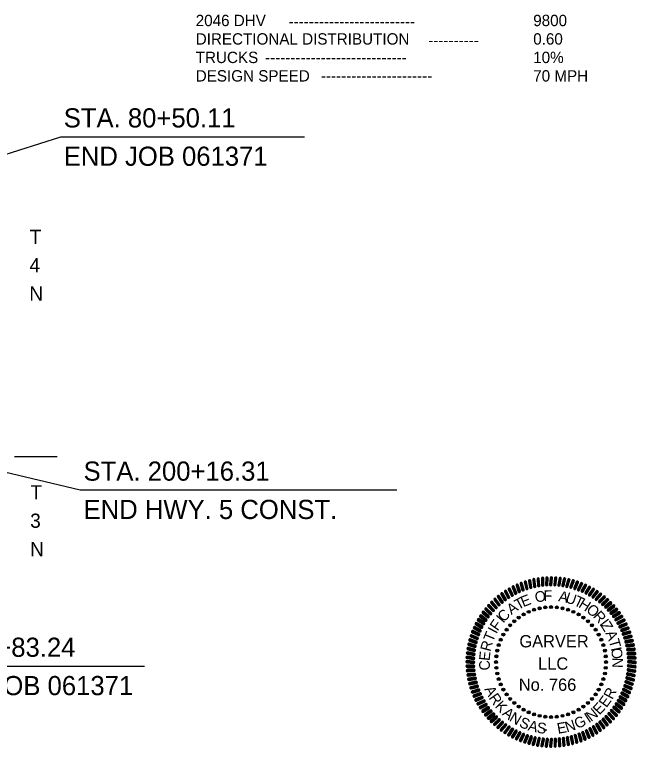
# Model space of a CAD drawing. Extents: x 1373878 to 1386598, y 1168333 to 1170533.
# Drawn here: x 1376117 to 1376992, y 1168417 to 1169449 of the extents above; entities that cross this region are included whole.
import ezdxf

# ---------------------------------------------------------------- set-up
doc = ezdxf.new("R2010")
doc.units = 0
for name, color, linetype in [('G-ANNO-STMP', 7, 'Continuous'), ('G-ANNO-TEXT', 7, 'Continuous'), ('R_Dimension', 7, 'Continuous'), ('R_Draft', 7, 'Continuous')]:
    doc.layers.add(name, color=color, linetype=linetype)

# ---------------------------------------------------------------- blocks, each defined once
blk = doc.blocks.new('SEALDO')
at = {"layer": 'G-ANNO-TEXT'}
for radius in [0.0396, 0.0305, 0.0213, 0.0122, 0.00305]:
    blk.add_circle((1.403, -0.456), radius, dxfattribs=at)
blk = doc.blocks.new('SEALRI')
at = {"layer": 'G-ANNO-TEXT'}
for p, q in [((-0.023, 2.258), (-0.038, 2.081)), ((-0.008, 2.281), (-0.028, 2.056)), ((0.004, 2.286), (-0.016, 2.049)), ((0.016, 2.285), (-0.004, 2.048)), ((0.028, 2.278), (0.008, 2.052)), ((0.023, 2.076), (0.038, 2.253))]:
    blk.add_line(p, q, dxfattribs=at)
for centre, start, end in [((0.008, 2.256), 355, 175), ((-0.008, 2.078), 175, 355)]:
    blk.add_arc(centre, 0.0305, start, end, dxfattribs=at)

msp = doc.modelspace()

# ---------------------------------------------------------------- linework, layer by layer
at = {"layer": 'R_Dimension'}
msp.add_line((1376117.2, 1168826.8), (1376177.2, 1168826.8), dxfattribs=at)
at = {"layer": 'R_Draft'}
for p, q in [((1376181.5, 1169276.8), (1375395.5, 1169025.7)), ((1376525.3, 1169276.8), (1376181.5, 1169276.8)), ((1376209.4, 1168779.3), (1375377.1, 1168978.1)), ((1376655.3, 1168779.3), (1376209.4, 1168779.3)), ((1376299.9, 1168531.2), (1375956.2, 1168531.2))]:
    msp.add_line(p, q, dxfattribs=at)

# ---------------------------------------------------------------- block references
at = {"layer": 'G-ANNO-STMP'}
for name, xscale, yscale, rotation in [('SEALRI', 52.49240596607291, 52.4924059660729, 20.99999999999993), ('SEALRI', 52.492405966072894, 52.4924059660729, 18), ('SEALRI', 52.4924059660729, 52.4924059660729, 15.000000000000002), ('SEALRI', 52.492405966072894, 52.492405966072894, 12.000000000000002), ('SEALRI', 52.492405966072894, 52.49240596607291, 9), ('SEALRI', 52.492405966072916, 52.49240596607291, 6), ('SEALRI', 52.492405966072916, 52.492405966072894, 3.0000000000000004), ('SEALRI', 52.49240596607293, 52.49240596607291, -2.9999999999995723), ('SEALRI', 52.4924059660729, 52.49240596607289, -5.9999999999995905), ('SEALRI', 52.492405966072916, 52.49240596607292, -8.999999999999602), ('SEALRI', 52.492405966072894, 52.492405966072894, -11.999999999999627), ('SEALRI', 52.4924059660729, 52.492405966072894, -14.999999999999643), ('SEALRI', 52.4924059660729, 52.4924059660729, -17.999999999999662), ('SEALRI', 52.4924059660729, 52.492405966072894, -20.999999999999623), ('SEALRI', 52.4924059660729, 52.492405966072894, 33), ('SEALRI', 52.4924059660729, 52.492405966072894, 30.00000000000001), ('SEALRI', 52.492405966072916, 52.492405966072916, 26.999999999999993), ('SEALRI', 52.49240596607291, 52.4924059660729, 23.99999999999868), ('SEALRI', 52.492405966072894, 52.4924059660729, -23.99999999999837), ('SEALRI', 52.492405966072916, 52.49240596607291, -26.9999999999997), ('SEALRI', 52.4924059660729, 52.49240596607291, -29.99999999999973), ('SEALRI', 52.4924059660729, 52.49240596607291, -32.999999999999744), ('SEALRI', 52.49240596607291, 52.4924059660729, 41.999999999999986), ('SEALRI', 52.49240596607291, 52.4924059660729, 38.999999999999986), ('SEALRI', 52.4924059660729, 52.492405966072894, 36), ('SEALRI', 52.4924059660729, 52.492405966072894, -35.999999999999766), ('SEALRI', 52.4924059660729, 52.4924059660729, -38.99999999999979), ('SEALRI', 52.4924059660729, 52.4924059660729, -41.99999999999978), ('SEALRI', 52.492405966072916, 52.49240596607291, 47.99999999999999), ('SEALRI', 52.4924059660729, 52.492405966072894, 44.999999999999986), ('SEALDO', 52.4924059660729, 52.49240596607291, 107.99999999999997), ('SEALRI', 52.49240596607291, 52.4924059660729, -44.99999999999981), ('SEALRI', 52.49240596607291, 52.4924059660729, -47.99999999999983), ('SEALRI', 52.4924059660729, 52.492405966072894, 54), ('SEALRI', 52.49240596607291, 52.4924059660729, 50.99999999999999), ('SEALDO', 52.4924059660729, 52.49240596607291, 138), ('SEALDO', 52.492405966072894, 52.49240596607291, 131.99999999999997), ('SEALDO', 52.492405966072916, 52.492405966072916, 125.99999999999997), ('SEALDO', 52.492405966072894, 52.4924059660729, 119.99999999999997), ('SEALDO', 52.4924059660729, 52.49240596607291, 113.99999999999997), ('SEALDO', 52.4924059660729, 52.49240596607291, 101.99999999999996), ('SEALDO', 52.492405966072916, 52.49240596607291, 95.99999999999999), ('SEALDO', 52.49240596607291, 52.4924059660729, 90), ('SEALDO', 52.492405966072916, 52.492405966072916, 83.99999999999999), ('SEALRI', 52.492405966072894, 52.4924059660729, -50.99999999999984), ('SEALRI', 52.4924059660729, 52.4924059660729, -53.99999999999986), ('SEALRI', 52.492405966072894, 52.4924059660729, 59.999999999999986), ('SEALRI', 52.49240596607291, 52.492405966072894, 56.99999999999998), ('SEALDO', 52.49240596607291, 52.4924059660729, 150), ('SEALDO', 52.492405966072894, 52.4924059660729, 144), ('SEALDO', 52.492405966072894, 52.4924059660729, 77.99999999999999), ('SEALDO', 52.492405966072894, 52.4924059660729, 72), ('SEALDO', 52.49240596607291, 52.49240596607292, 66.00000000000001), ('SEALRI', 52.49240596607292, 52.49240596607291, -56.999999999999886), ('SEALRI', 52.4924059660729, 52.4924059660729, -59.99999999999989), ('SEALRI', 52.49240596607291, 52.4924059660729, 65.99999999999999), ('SEALRI', 52.492405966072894, 52.49240596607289, 63), ('SEALDO', 52.4924059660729, 52.49240596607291, 156.00000000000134), ('SEALDO', 52.49240596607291, 52.4924059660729, 60.00000000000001), ('SEALRI', 52.49240596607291, 52.492405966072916, -62.99999999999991), ('SEALRI', 52.49240596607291, 52.49240596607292, -65.99999999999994), ('SEALRI', 52.492405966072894, 52.4924059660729, 72), ('SEALRI', 52.49240596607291, 52.4924059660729, 68.99999999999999), ('SEALDO', 52.49240596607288, 52.4924059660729, 168.00000000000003), ('SEALDO', 52.492405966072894, 52.49240596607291, 162.00000000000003), ('SEALDO', 52.4924059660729, 52.492405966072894, 54), ('SEALDO', 52.49240596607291, 52.4924059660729, 48.000000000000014), ('SEALRI', 52.49240596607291, 52.4924059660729, -68.99999999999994), ('SEALRI', 52.4924059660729, 52.4924059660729, -71.99999999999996), ('SEALRI', 52.4924059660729, 52.49240596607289, 75.00000000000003), ('SEALDO', 52.492405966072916, 52.49240596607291, 174.00000000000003), ('SEALDO', 52.492405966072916, 52.49240596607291, 42.00000000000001), ('SEALRI', 52.49240596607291, 52.4924059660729, -74.99999999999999), ('SEALRI', 52.492405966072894, 52.49240596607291, 81), ('SEALRI', 52.492405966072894, 52.49240596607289, 78.00000000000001), ('SEALDO', 52.49240596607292, 52.49240596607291, -173.99999999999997), ('SEALDO', 52.49240596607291, 52.4924059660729, -179.99999999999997), ('SEALDO', 52.4924059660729, 52.492405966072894, 36), ('SEALDO', 52.49240596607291, 52.4924059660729, 29.999999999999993), ('SEALRI', 52.492405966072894, 52.492405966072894, -78), ('SEALRI', 52.492405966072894, 52.49240596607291, -81.00000000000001), ('SEALRI', 52.4924059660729, 52.49240596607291, 87.00000000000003), ('SEALRI', 52.492405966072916, 52.49240596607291, 84.00000000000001), ('SEALDO', 52.492405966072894, 52.4924059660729, -167.99999999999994), ('SEALDO', 52.49240596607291, 52.4924059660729, 23.99999999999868), ('SEALRI', 52.492405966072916, 52.49240596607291, -84.00000000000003), ('SEALRI', 52.4924059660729, 52.4924059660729, -87.00000000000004), ('SEALRI', 52.49240596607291, 52.4924059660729, 90.00000000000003), ('SEALDO', 52.4924059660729, 52.492405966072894, -161.99999999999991), ('SEALDO', 52.492405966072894, 52.4924059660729, 18), ('SEALRI', 52.49240596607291, 52.4924059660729, -90.00000000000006), ('SEALRI', 52.492405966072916, 52.492405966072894, 93), ('SEALRI', 52.492405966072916, 52.492405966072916, 96.00000000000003), ('SEALDO', 52.4924059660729, 52.4924059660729, -156.00000000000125), ('SEALDO', 52.492405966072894, 52.492405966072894, 12.000000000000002), ('SEALRI', 52.4924059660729, 52.492405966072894, -96.0000000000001), ('SEALRI', 52.492405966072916, 52.49240596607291, -93.00000000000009), ('SEALRI', 52.49240596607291, 52.492405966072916, 99.00000000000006), ('SEALRI', 52.492405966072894, 52.49240596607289, 102.00000000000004), ('SEALDO', 52.4924059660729, 52.49240596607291, -149.99999999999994), ('SEALDO', 52.492405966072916, 52.49240596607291, -143.99999999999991), ('SEALDO', 52.492405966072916, 52.49240596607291, 6), ('SEALRI', 52.492405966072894, 52.492405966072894, -102.00000000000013), ('SEALRI', 52.49240596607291, 52.492405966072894, -99.00000000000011), ('SEALRI', 52.49240596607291, 52.4924059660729, 105.00000000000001), ('SEALRI', 52.4924059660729, 52.4924059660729, 108.00000000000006), ('SEALDO', 52.492405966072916, 52.49240596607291, -137.9999999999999), ('SEALDO', 52.4924059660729, 52.4924059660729, -6.000000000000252), ('SEALRI', 52.49240596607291, 52.492405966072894, -108.00000000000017), ('SEALRI', 52.49240596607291, 52.4924059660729, -105.00000000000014), ('SEALRI', 52.4924059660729, 52.492405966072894, 111.00000000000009), ('SEALRI', 52.49240596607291, 52.492405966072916, 114.00000000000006), ('SEALDO', 52.4924059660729, 52.49240596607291, -131.99999999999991), ('SEALDO', 52.4924059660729, 52.49240596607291, -125.9999999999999), ('SEALDO', 52.492405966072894, 52.4924059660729, -18.000000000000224), ('SEALDO', 52.492405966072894, 52.492405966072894, -12.000000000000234), ('SEALRI', 52.49240596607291, 52.492405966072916, -114.0000000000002), ('SEALRI', 52.4924059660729, 52.49240596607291, -111.00000000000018), ('SEALRI', 52.4924059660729, 52.49240596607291, 117.00000000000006), ('SEALRI', 52.492405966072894, 52.4924059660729, 120.00000000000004), ('SEALDO', 52.4924059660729, 52.4924059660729, -119.99999999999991), ('SEALDO', 52.49240596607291, 52.492405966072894, -23.999999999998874), ('SEALRI', 52.4924059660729, 52.4924059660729, -120.00000000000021), ('SEALRI', 52.49240596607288, 52.4924059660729, -117.00000000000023), ('SEALRI', 52.4924059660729, 52.492405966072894, 123.00000000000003), ('SEALRI', 52.4924059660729, 52.49240596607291, 126.00000000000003), ('SEALDO', 52.49240596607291, 52.492405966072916, -113.99999999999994), ('SEALDO', 52.4924059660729, 52.4924059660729, -107.99999999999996), ('SEALDO', 52.4924059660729, 52.492405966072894, -42.00000000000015), ('SEALDO', 52.4924059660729, 52.4924059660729, -36.00000000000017), ('SEALDO', 52.4924059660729, 52.492405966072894, -30.00000000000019), ('SEALRI', 52.4924059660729, 52.4924059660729, -126.00000000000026), ('SEALRI', 52.492405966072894, 52.49240596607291, -123.00000000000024), ('SEALRI', 52.49240596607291, 52.4924059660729, 129.00000000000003), ('SEALRI', 52.4924059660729, 52.4924059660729, 132), ('SEALRI', 52.4924059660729, 52.49240596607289, 135), ('SEALDO', 52.492405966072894, 52.49240596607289, -101.99999999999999), ('SEALDO', 52.492405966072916, 52.49240596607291, -96), ('SEALDO', 52.49240596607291, 52.4924059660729, -90.00000000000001), ('SEALDO', 52.492405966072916, 52.49240596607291, -84.00000000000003), ('SEALDO', 52.4924059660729, 52.49240596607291, -78.00000000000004), ('SEALDO', 52.4924059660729, 52.49240596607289, -72.00000000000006), ('SEALDO', 52.492405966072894, 52.49240596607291, -66.00000000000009), ('SEALDO', 52.4924059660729, 52.49240596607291, -60.0000000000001), ('SEALDO', 52.4924059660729, 52.4924059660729, -54.000000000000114), ('SEALDO', 52.49240596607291, 52.492405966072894, -48.00000000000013), ('SEALRI', 52.492405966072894, 52.4924059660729, -135.00000000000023), ('SEALRI', 52.49240596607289, 52.4924059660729, -132.00000000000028), ('SEALRI', 52.492405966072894, 52.4924059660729, -129.00000000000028), ('SEALRI', 52.4924059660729, 52.49240596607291, 138), ('SEALRI', 52.492405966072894, 52.4924059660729, 140.99999999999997), ('SEALRI', 52.4924059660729, 52.4924059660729, -141.0000000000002), ('SEALRI', 52.4924059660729, 52.492405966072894, -138.00000000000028), ('SEALRI', 52.492405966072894, 52.4924059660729, 144), ('SEALRI', 52.4924059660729, 52.492405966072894, 146.99999999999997), ('SEALRI', 52.4924059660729, 52.49240596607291, 149.99999999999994), ('SEALRI', 52.492405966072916, 52.49240596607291, 152.99999999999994), ('SEALRI', 52.4924059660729, 52.49240596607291, -153.00000000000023), ('SEALRI', 52.49240596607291, 52.492405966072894, -150.00000000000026), ('SEALRI', 52.4924059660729, 52.49240596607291, -147.00000000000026), ('SEALRI', 52.49240596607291, 52.49240596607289, -144.00000000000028), ('SEALRI', 52.4924059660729, 52.49240596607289, 156.00000000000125), ('SEALRI', 52.4924059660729, 52.4924059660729, 159), ('SEALRI', 52.49240596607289, 52.49240596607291, 161.99999999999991), ('SEALRI', 52.4924059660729, 52.49240596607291, 164.99999999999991), ('SEALRI', 52.492405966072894, 52.49240596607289, 167.99999999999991), ('SEALRI', 52.492405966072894, 52.4924059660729, -168.0000000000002), ('SEALRI', 52.4924059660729, 52.49240596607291, -165.0000000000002), ('SEALRI', 52.4924059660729, 52.4924059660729, -162.0000000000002), ('SEALRI', 52.4924059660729, 52.49240596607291, -159.00000000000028), ('SEALRI', 52.492405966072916, 52.49240596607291, -156.00000000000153), ('SEALRI', 52.49240596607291, 52.492405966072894, 170.9999999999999), ('SEALRI', 52.4924059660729, 52.4924059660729, 173.9999999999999), ('SEALRI', 52.492405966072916, 52.49240596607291, 176.9999999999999), ('SEALRI', 52.49240596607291, 52.4924059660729, 179.99999999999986), ('SEALRI', 52.492405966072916, 52.49240596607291, -177.00000000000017), ('SEALRI', 52.4924059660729, 52.492405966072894, -174.00000000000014), ('SEALRI', 52.49240596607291, 52.49240596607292, -171.00000000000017)]:
    msp.add_blockref(name, (1376872.3, 1168537.3), dxfattribs=dict(at, xscale=xscale, yscale=yscale, rotation=rotation))
at = {"layer": 'G-ANNO-STMP', "xscale": 52.49240596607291, "yscale": 52.4924059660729}
for name in ['SEALRI', 'SEALDO']:
    msp.add_blockref(name, (1376872.3, 1168537.3), dxfattribs=at)

# ---------------------------------------------------------------- texts
at = {"layer": 'G-ANNO-STMP'}
for s, rotation, p in [('F', 1.6104, (1376861.9, 1168623.2)), ('T', 28.2771, (1376825.9, 1168610.2)), ('E', 21.6104, (1376833.1, 1168614.5)), ('O', 8.2771, (1376850.5, 1168621.2)), ('A', 348.2771, (1376881.9, 1168623.3)), ('U', 341.2772, (1376891.3, 1168621.8)), ('T', 334.9438, (1376903.1, 1168618)), ('A', 34.9438, (1376816.4, 1168603.3)), ('H', 328.2771, (1376909.9, 1168615.3)), ('O', 319.7874, (1376920.7, 1168609.2)), ('C', 44.3881, (1376805.7, 1168592.8)), ('R', 311.9933, (1376930.5, 1168601.3)), ('F', 54.9438, (1376797.1, 1168580.2)), ('I', 49.7408, (1376805, 1168591.2)), ('I', 307.0081, (1376939.7, 1168591)), ('I', 61.6104, (1376795.4, 1168576.2)), ('Z', 301.6104, (1376941.5, 1168589.2)), ('T', 67.4314, (1376790.3, 1168564.6)), ('A', 292.9752, (1376948.5, 1168578.3)), ('R', 74.9438, (1376786.8, 1168551.3)), ('T', 286.3085, (1376953.2, 1168567.5)), ('I', 281.6104, (1376956.2, 1168556.9)), ('O', 276.4823, (1376956.8, 1168556.4)), ('E', 83.8985, (1376785.7, 1168538.5)), ('C', 91.8842, (1376786.4, 1168525.7)), ('N', 268.2771, (1376958.7, 1168543.7)), ('A', 296.5747, (1376778.1, 1168499.3)), ('R', 304.6183, (1376784, 1168486.9)), ('R', 63.0959, (1376958.7, 1168483.7)), ('K', 313.3805, (1376792.4, 1168474.4)), ('E', 54.7309, (1376950.3, 1168472.2)), ('E', 46.6807, (1376940.4, 1168462)), ('A', 321.2584, (1376802.6, 1168463.4)), ('N', 329.1099, (1376812.4, 1168455.1)), ('I', 32.979, (1376925.3, 1168451)), ('N', 38.9821, (1376928.8, 1168452.8)), ('S', 337.6294, (1376826.3, 1168446.7)), ('A', 345.4073, (1376838.9, 1168441.4)), ('S', 352.8046, (1376851.6, 1168437.8)), ('E', 10.0695, (1376882.1, 1168436.2)), ('N', 17.8686, (1376894.6, 1168438.1)), ('G', 26.4132, (1376909.4, 1168442.6)), ('-', 0.8385, (1376860.7, 1168435.8))]:
    msp.add_text(s, height=15, rotation=rotation, dxfattribs=at).set_placement(p)
for s, p in [('GARVER', (1376827.7, 1168558)), ('LLC', (1376854.1, 1168526.6)), ('No. 766', (1376826.9, 1168496.8))]:
    msp.add_text(s, height=17.28, dxfattribs=at).set_placement(p)
at = {"layer": 'R_Draft'}
for s, height, p in [('2046 DHV', 16, (1376372.1, 1169433)), ('9800', 16, (1376847.2, 1169433)), ('-------------------------', 16, (1376502.8, 1169431.6)), ('DIRECTIONAL DISTRIBUTION', 16, (1376372.1, 1169407)), ('0.60', 16, (1376847.2, 1169407)), ('----------', 16, (1376699.4, 1169405.2)), ('TRUCKS', 16, (1376372.1, 1169381)), ('10%', 16, (1376847.2, 1169381)), ('----------------------------', 16, (1376469.7, 1169381)), ('DESIGN SPEED', 16, (1376372.1, 1169355)), ('70 MPH', 16, (1376847.2, 1169355)), ('----------------------', 16, (1376548.3, 1169355)), ('STA. 80+50.11', 27, (1376186.3, 1169290.3)), ('END JOB 061371', 27, (1376186.3, 1169236.3)), ('T', 20, (1376138.4, 1169126.3)), ('4', 20, (1376138.1, 1169086.3)), ('N', 20, (1376137.9, 1169046.3)), ('STA. 200+16.31', 27, (1376214.2, 1168792.8)), ('T', 20, (1376139.4, 1168766.4)), ('END HWY. 5 CONST.', 27, (1376214.2, 1168738.8)), ('3', 20, (1376139.1, 1168726.4)), ('N', 20, (1376138.9, 1168686.4)), ('STA. 53+83.24', 27, (1375960.9, 1168544.7)), ('BEGIN JOB 061371', 27, (1375960.9, 1168490.7))]:
    msp.add_text(s, height=height, dxfattribs=at).set_placement(p)

doc.saveas('drawing.dxf')
